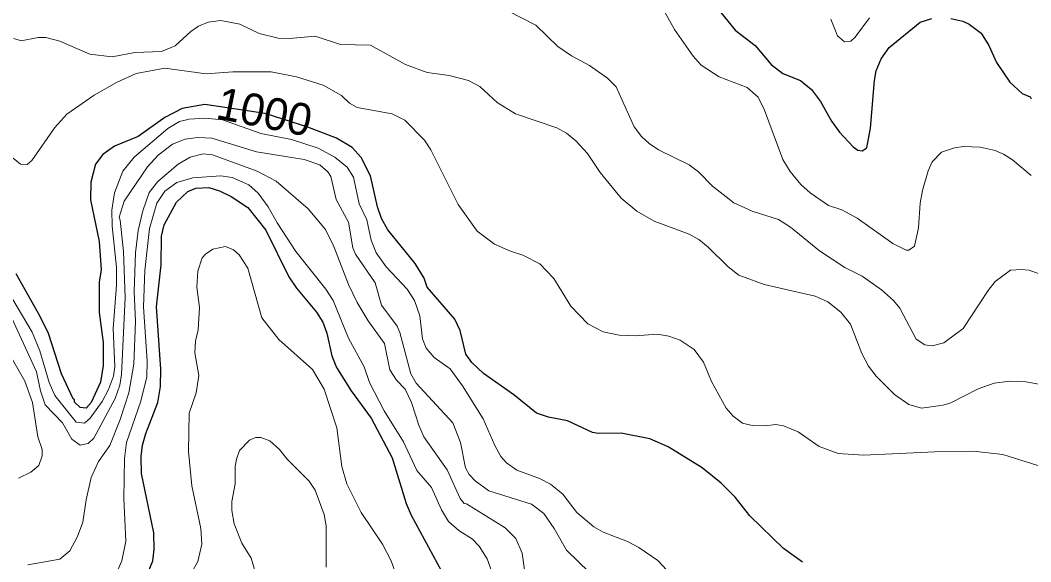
# Model space of a CAD drawing. Extents: x 265 to 291.4, y 7731.5 to 7759.6.
# Drawn here: x 287.145 to 289.671, y 7737.4 to 7738.754 of the extents above; entities that cross this region are included whole.
import ezdxf
from ezdxf.enums import TextEntityAlignment as Align

# ---------------------------------------------------------------- set-up
doc = ezdxf.new("R2010")
doc.units = 0
doc.header["$LTSCALE"] = 0.032
for name, color, linetype, lineweight in [('1', 7, 'Continuous', 25), ('2', 7, 'Continuous', 13), ('61', 7, 'Continuous', 13)]:
    doc.layers.add(name, color=color, linetype=linetype, lineweight=lineweight)

msp = doc.modelspace()

# ---------------------------------------------------------------- linework, layer by layer
at = {"layer": '1'}
for points in [[(288.8787, 7738.7949), (288.932, 7738.7297), (288.9822, 7738.6907), (289.0227, 7738.6438), (289.0513, 7738.6215), (289.0959, 7738.6032), (289.123, 7738.5809), (289.146, 7738.5507), (289.1731, 7738.5022), (289.1929, 7738.4743), (289.2272, 7738.4377), (289.2391, 7738.4298), (289.2502, 7738.4274), (289.2614, 7738.4354), (289.2709, 7738.4847), (289.2804, 7738.604), (289.2852, 7738.6279), (289.2971, 7738.6581), (289.3178, 7738.6859), (289.395, 7738.7496), (289.4237, 7738.7583)], [(289.4714, 7738.7583), (289.5016, 7738.7519), (289.5175, 7738.7448), (289.5477, 7738.7217), (289.5668, 7738.6915), (289.5859, 7738.6485), (289.6193, 7738.5992), (289.6503, 7738.5714), (289.6695, 7738.5626), (289.6726, 7738.5579)], [(289.1007, 7737.3996), (289.053, 7737.4338), (288.9694, 7737.515), (288.932, 7737.5619), (288.8978, 7737.5969), (288.8501, 7737.6351), (288.765, 7737.6876), (288.7189, 7737.7075), (288.6473, 7737.7218), (288.59, 7737.721), (288.5757, 7737.7234), (288.5136, 7737.7528), (288.4659, 7737.7624), (288.4357, 7737.7719), (288.3792, 7737.818), (288.3036, 7737.8713), (288.2742, 7737.8984), (288.2591, 7737.9199), (288.2447, 7737.9788), (288.2312, 7738.0074), (288.1628, 7738.0869), (288.1548, 7738.1092), (288.1326, 7738.1458), (288.0641, 7738.2301), (288.0482, 7738.2588), (288.0379, 7738.2874), (288.0204, 7738.3654), (287.9973, 7738.4115), (287.9751, 7738.4362), (287.9361, 7738.4592), (287.8637, 7738.4871), (287.7572, 7738.521), (287.6068, 7738.5435), (287.5495, 7738.534), (287.5065, 7738.5109), (287.4397, 7738.464), (287.3809, 7738.4393), (287.3514, 7738.4186), (287.3331, 7738.3948), (287.3212, 7738.3494), (287.3204, 7738.3049), (287.3426, 7738.2015), (287.3474, 7738.1299), (287.3426, 7738.0997), (287.3426, 7738.0233), (287.3522, 7737.9485), (287.3522, 7737.8912), (287.3458, 7737.8491), (287.3228, 7737.799), (287.31, 7737.7846), (287.2949, 7737.7862), (287.2806, 7737.7998), (287.2806, 7737.8061), (287.2774, 7737.8077), (287.248, 7737.8706), (287.2154, 7737.9708), (287.1947, 7738.0138), (287.135, 7738.1203)], [(287.4651, 7737.3742), (287.4763, 7737.4028), (287.4795, 7737.4315), (287.4787, 7737.4728), (287.4484, 7737.6208), (287.4476, 7737.6637), (287.4508, 7737.6924), (287.4588, 7737.721), (287.489, 7737.799), (287.4954, 7737.8387), (287.4962, 7737.8817), (287.4858, 7738.0376), (287.4978, 7738.1426), (287.4986, 7738.2142), (287.5049, 7738.2429), (287.5359, 7738.2993), (287.5638, 7738.3264), (287.5837, 7738.3343), (287.6163, 7738.3359), (287.6434, 7738.3279), (287.672, 7738.3136), (287.7142, 7738.2858), (287.7587, 7738.2293), (287.8168, 7738.1124), (287.8358, 7738.0845), (287.886, 7738.0249), (287.9019, 7737.9994), (287.9114, 7737.9724), (287.9241, 7737.9151), (287.9361, 7737.8865), (287.9727, 7737.8276), (288.022, 7737.7592), (288.0745, 7737.6606), (288.1095, 7737.546), (288.1222, 7737.5174), (288.1986, 7737.3774)]]:
    msp.add_lwpolyline(points, dxfattribs=at)
at = {"layer": '2'}
for points in [[(289.7148, 7738.1116), (289.6671, 7738.1291), (289.648, 7738.1315), (289.6209, 7738.1291), (289.5828, 7738.1012), (289.5652, 7738.079), (289.5024, 7737.9835), (289.4539, 7737.9477), (289.4253, 7737.9406), (289.4062, 7737.9429), (289.3847, 7737.9573), (289.3441, 7738.0344), (289.3282, 7738.0535), (289.298, 7738.0806), (289.2502, 7738.1148), (289.2065, 7738.1362), (289.1436, 7738.1776), (289.0705, 7738.2373), (289.041, 7738.2564), (288.975, 7738.277), (288.9289, 7738.2977), (288.8756, 7738.3391), (288.8405, 7738.3749), (288.8175, 7738.3932), (288.7411, 7738.4306), (288.7173, 7738.4465), (288.6982, 7738.464), (288.6799, 7738.4879), (288.6353, 7738.5881), (288.613, 7738.6096), (288.5685, 7738.6414), (288.5232, 7738.6652), (288.489, 7738.6883), (288.4341, 7738.7416), (288.3641, 7738.7774)], [(288.7554, 7738.7758), (288.7809, 7738.7313), (288.827, 7738.6645), (288.8477, 7738.6422), (288.8923, 7738.6127), (288.9623, 7738.5857), (288.9901, 7738.5618), (289.006, 7738.5292), (289.0514, 7738.4059), (289.0697, 7738.3765), (289.0967, 7738.3439), (289.1198, 7738.3224), (289.1659, 7738.2914), (289.1993, 7738.2802), (289.2375, 7738.2595), (289.3266, 7738.1959), (289.36, 7738.1792), (289.3664, 7738.1792), (289.3807, 7738.1896), (289.391, 7738.2349), (289.395, 7738.2969), (289.4006, 7738.3288), (289.4149, 7738.3781), (289.4252, 7738.4004), (289.4483, 7738.4242), (289.4809, 7738.4354), (289.5032, 7738.4385), (289.5446, 7738.4369), (289.5828, 7738.4282), (289.6034, 7738.4194), (289.6257, 7738.4051), (289.6726, 7738.3661)], [(287.1287, 7738.709), (287.147, 7738.7026), (287.1899, 7738.7114), (287.209, 7738.7114), (287.244, 7738.7018), (287.3188, 7738.6692), (287.3745, 7738.6629), (287.4318, 7738.6732), (287.4986, 7738.6764), (287.532, 7738.6899), (287.5718, 7738.7265), (287.5909, 7738.7392), (287.6147, 7738.7496), (287.6465, 7738.7535), (287.6943, 7738.7448), (287.742, 7738.7209), (287.7897, 7738.7098), (287.8184, 7738.7082), (287.882, 7738.7146), (287.9456, 7738.6939), (288.0204, 7738.6923), (288.1079, 7738.6438), (288.162, 7738.6239), (288.2177, 7738.6159), (288.2654, 7738.604), (288.2941, 7738.5889), (288.337, 7738.5483), (288.3832, 7738.5205), (288.4866, 7738.4855), (288.5104, 7738.4719), (288.5343, 7738.4528), (288.5629, 7738.421), (288.5947, 7738.3733), (288.6473, 7738.3097), (288.6862, 7738.277), (288.73, 7738.2516), (288.8175, 7738.2198), (288.8414, 7738.2062), (288.8652, 7738.1872), (288.9145, 7738.1378), (288.9416, 7738.1171), (289.0052, 7738.0933), (289.1325, 7738.0647), (289.1643, 7738.0503), (289.1969, 7738.0241), (289.2208, 7737.9947), (289.2494, 7737.9215), (289.2661, 7737.8897), (289.2852, 7737.8642), (289.3306, 7737.8189), (289.3664, 7737.7934), (289.3982, 7737.7846), (289.4523, 7737.7918), (289.4714, 7737.7982), (289.5398, 7737.8332), (289.5796, 7737.8467), (289.6193, 7737.8523), (289.6591, 7737.8507), (289.8564, 7737.8141)], [(289.2685, 7738.7599), (289.2327, 7738.7122), (289.2216, 7738.7018), (289.2057, 7738.7002), (289.1882, 7738.7154), (289.1715, 7738.7567)], [(289.6894, 7737.6415), (289.6018, 7737.6685), (289.5271, 7737.6773), (289.4316, 7737.6757), (289.2534, 7737.6669), (289.1898, 7737.6709), (289.1421, 7737.6884), (289.0896, 7737.725), (289.053, 7737.7401), (289.0339, 7737.7433), (289.0068, 7737.7401), (288.975, 7737.7409), (288.9511, 7737.7473), (288.9273, 7737.7648), (288.9098, 7737.7847), (288.8732, 7737.8515), (288.8533, 7737.8992), (288.8302, 7737.931), (288.7952, 7737.9541), (288.7666, 7737.9644), (288.738, 7737.9692), (288.6823, 7737.9652), (288.6425, 7737.9668), (288.6027, 7737.9756), (288.5637, 7737.9954), (288.5216, 7738.0392), (288.4794, 7738.1084), (288.4444, 7738.145), (288.4015, 7738.1673), (288.3704, 7738.1768), (288.3307, 7738.1943), (288.2877, 7738.2269), (288.24, 7738.2938), (288.1715, 7738.4306), (288.1556, 7738.4545), (288.1063, 7738.5046), (288.0745, 7738.5205), (287.987, 7738.5364), (287.9679, 7738.5467), (287.948, 7738.5658), (287.9027, 7738.5921), (287.8359, 7738.6127), (287.7722, 7738.6255), (287.6768, 7738.6255), (287.61, 7738.6199), (287.5065, 7738.6342), (287.4349, 7738.6207), (287.3856, 7738.5984), (287.3299, 7738.5666), (287.2615, 7738.5197), (287.2313, 7738.4863), (287.174, 7738.4035), (287.1621, 7738.394), (287.1454, 7738.3948), (287.1271, 7738.4091)], [(287.1136, 7738.079), (287.1748, 7737.9748), (287.1939, 7737.9278), (287.217, 7737.8483), (287.2313, 7737.8165), (287.2846, 7737.7496), (287.3061, 7737.7473), (287.3196, 7737.7592), (287.3498, 7737.8014), (287.3657, 7737.8308), (287.3785, 7737.8642), (287.3816, 7737.8881), (287.3777, 7737.9835), (287.3856, 7738.0917), (287.3856, 7738.1363), (287.3745, 7738.2397), (287.3737, 7738.2794), (287.3808, 7738.3224), (287.4015, 7738.3773), (287.4302, 7738.4123), (287.5137, 7738.4839), (287.5431, 7738.5014), (287.567, 7738.5069), (287.6068, 7738.5093), (287.6504, 7738.5052), (287.7468, 7738.4711), (287.8231, 7738.456), (287.89, 7738.4346), (287.9313, 7738.4123), (287.9624, 7738.3868), (287.9783, 7738.3622), (287.9926, 7738.2954), (288.0117, 7738.2556), (288.022, 7738.2047), (288.0347, 7738.1729), (288.0602, 7738.1378), (288.1127, 7738.0822), (288.131, 7738.0535), (288.1437, 7738.0153), (288.1509, 7737.9581), (288.1596, 7737.9342), (288.1795, 7737.9111), (288.2201, 7737.8825), (288.2511, 7737.8403), (288.3028, 7737.7576), (288.3314, 7737.6908), (288.3466, 7737.6637), (288.3609, 7737.6478), (288.3863, 7737.6295), (288.4436, 7737.6088), (288.4707, 7737.5945), (288.5017, 7737.5699), (288.5367, 7737.5237), (288.5789, 7737.4879), (288.6027, 7737.4744), (288.6632, 7737.4513), (288.6918, 7737.4362), (288.7387, 7737.4036), (288.7721, 7737.3678)], [(288.5677, 7737.3742), (288.5104, 7737.4299), (288.4802, 7737.484), (288.454, 7737.5213), (288.4229, 7737.5444), (288.3163, 7737.5778), (288.2821, 7737.6025), (288.2678, 7737.6184), (288.2583, 7737.6351), (288.2455, 7737.6987), (288.2264, 7737.7481), (288.135, 7737.8467), (288.1214, 7737.8706), (288.0944, 7737.974), (288.0872, 7737.9899), (288.0483, 7738.0424), (288.0323, 7738.0981), (287.983, 7738.1697), (287.9767, 7738.1856), (287.9655, 7738.2492), (287.9353, 7738.3065), (287.9218, 7738.3638), (287.9138, 7738.3757), (287.8939, 7738.3932), (287.855, 7738.4059), (287.7356, 7738.425), (287.6243, 7738.4592), (287.5893, 7738.4608), (287.5575, 7738.4568), (287.5256, 7738.4441), (287.4898, 7738.4171), (287.4636, 7738.3876), (287.4047, 7738.3017), (287.392, 7738.2619), (287.3952, 7738.2548), (287.4031, 7738.176), (287.4071, 7738.0615), (287.3983, 7737.869), (287.3944, 7737.8419), (287.3824, 7737.8085), (287.3291, 7737.7099), (287.3148, 7737.6963), (287.2949, 7737.6924), (287.2743, 7737.7067), (287.2504, 7737.7481), (287.2074, 7737.7926), (287.1955, 7737.8276), (287.1859, 7737.8753), (287.1199, 7738.0185)], [(287.1637, 7737.3933), (287.244, 7737.4068), (287.2687, 7737.4275), (287.2886, 7737.4633), (287.3013, 7737.4999), (287.31, 7737.5556), (287.3228, 7737.6112), (287.3411, 7737.651), (287.3689, 7737.6908), (287.3952, 7737.756), (287.4166, 7737.8228), (287.4294, 7737.8944), (287.4333, 7738.001), (287.4302, 7738.0758), (287.4333, 7738.1729), (287.4397, 7738.2285), (287.4516, 7738.2779), (287.4675, 7738.324), (287.489, 7738.351), (287.5399, 7738.3948), (287.5702, 7738.4123), (287.602, 7738.4202), (287.6259, 7738.4179), (287.7372, 7738.3773), (287.785, 7738.3518), (287.8645, 7738.2826), (287.9082, 7738.2309), (287.9289, 7738.1888), (287.9655, 7738.0933), (287.987, 7738.0488), (288.0148, 7738.0026), (288.0554, 7737.9461), (288.0689, 7737.8801), (288.0856, 7737.8547), (288.1071, 7737.8324), (288.123, 7737.799), (288.1413, 7737.7417), (288.154, 7737.7131), (288.2121, 7737.6303), (288.2447, 7737.5587), (288.2551, 7737.546), (288.2607, 7737.5452), (288.3577, 7737.4855), (288.3839, 7737.4585), (288.3999, 7737.4219), (288.4102, 7737.3503)], [(288.3243, 7737.3758), (288.3124, 7737.4076), (288.2925, 7737.4394), (288.2758, 7737.4569), (288.2416, 7737.4784), (288.2161, 7737.5015), (288.1986, 7737.5301), (288.1731, 7737.5858), (288.1365, 7737.6287), (288.1031, 7737.7003), (288.0546, 7737.7775), (288.018, 7737.8483), (288.0045, 7737.8881), (287.9655, 7737.9597), (287.9273, 7738.0535), (287.909, 7738.0822), (287.8343, 7738.176), (287.7873, 7738.2476), (287.7651, 7738.2874), (287.7396, 7738.3216), (287.7165, 7738.3431), (287.6752, 7738.3614), (287.6465, 7738.3653), (287.5765, 7738.3606), (287.5368, 7738.3486), (287.5065, 7738.3272), (287.4866, 7738.2969), (287.4683, 7738.2333), (287.4564, 7738.1283), (287.4532, 7738.0376), (287.462, 7737.9024), (287.4612, 7737.8626), (287.4469, 7737.8022), (287.4111, 7737.6987), (287.4055, 7737.659), (287.4039, 7737.5587), (287.4087, 7737.4521), (287.3991, 7737.4028), (287.3785, 7737.3551)], [(287.5733, 7737.3726), (287.5893, 7737.4012), (287.5988, 7737.4442), (287.5964, 7737.484), (287.5741, 7737.5906), (287.5654, 7737.6765), (287.5678, 7737.7719), (287.5853, 7737.8228), (287.5916, 7737.8658), (287.5813, 7737.9231), (287.5829, 7737.9517), (287.5901, 7737.9803), (287.5932, 7738.036), (287.5869, 7738.0869), (287.5893, 7738.1267), (287.5996, 7738.1601), (287.6083, 7738.1697), (287.6267, 7738.1816), (287.6585, 7738.1887), (287.6784, 7738.18), (287.6927, 7738.1681), (287.7142, 7738.1347), (287.7492, 7738.0106), (287.7913, 7737.9565), (287.8756, 7737.8809), (287.9051, 7737.8324), (287.9369, 7737.7353), (287.9488, 7737.6383), (287.9615, 7737.5953), (287.9973, 7737.5237), (288.0506, 7737.4442), (288.0721, 7737.4028), (288.0825, 7737.3742)], [(287.0897, 7737.9676), (287.1565, 7737.8523), (287.1756, 7737.799), (287.1891, 7737.7131), (287.1995, 7737.6812), (287.2003, 7737.6653), (287.1915, 7737.6415), (287.1716, 7737.6247), (287.1406, 7737.6096)], [(287.9098, 7737.3869), (287.9098, 7737.4903), (287.9051, 7737.519), (287.8828, 7737.5794), (287.8677, 7737.6017), (287.812, 7737.6574), (287.7929, 7737.6812), (287.769, 7737.7027), (287.7468, 7737.7115), (287.7332, 7737.7115), (287.7181, 7737.7043), (287.6935, 7737.6788), (287.6855, 7737.6574), (287.6823, 7737.6383), (287.6823, 7737.5953), (287.6744, 7737.5508), (287.6744, 7737.5285), (287.6799, 7737.4951), (287.699, 7737.4474), (287.7221, 7737.4092), (287.7356, 7737.3646)]]:
    msp.add_lwpolyline(points, dxfattribs=at)

# ---------------------------------------------------------------- texts
at = {"layer": '61'}
msp.add_text('1000', height=0.08, rotation=348.67, dxfattribs=at).set_placement((287.748, 7738.4861), align=Align.CENTER)

doc.saveas('drawing.dxf')
